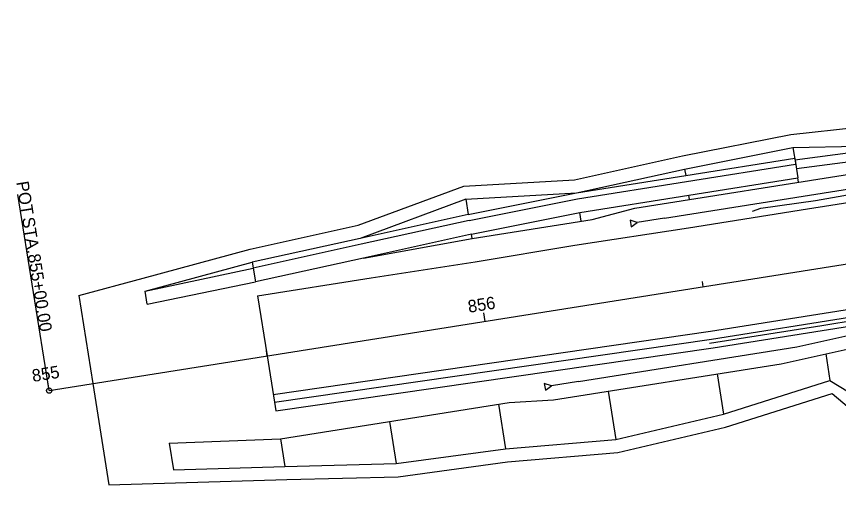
# Model space of a CAD drawing. Extents: x 115987 to 120394, y 324408 to 325987.
# Drawn here: x 117045 to 117231.2, y 325394.5 to 325501.7 of the extents above; entities that cross this region are included whole.
import ezdxf

# ---------------------------------------------------------------- set-up
doc = ezdxf.new("R2010")
doc.units = 0
for name, color, linetype in [('DT_X_Break_Line', 7, 'Continuous'), ('DT_X_Contour_Major', 7, 'Continuous'), ('DT_X_Contour_Minor', 7, 'Continuous'), ('DT_X_Terrain_Boundary', 7, 'Continuous'), ('DT_X_Triangles', 7, 'Continuous'), ('DT_X_Void', 7, 'Continuous'), ('PV_X_EOP', 7, 'Continuous'), ('PV_X_Shoulder', 7, 'Continuous'), ('RD_X_GR_Lt', 7, 'Continuous'), ('RW_X_CL_100_Stations', 7, 'Continuous'), ('RW_X_Esmt_LA', 7, 'Continuous'), ('RW_X_Text', 7, 'Continuous'), ('SV_X_Break_Lines', 7, 'Continuous'), ('UT_X_Gas_Cells', 7, 'Continuous')]:
    doc.layers.add(name, color=color, linetype=linetype)

msp = doc.modelspace()

# ---------------------------------------------------------------- linework, layer by layer
at = {"layer": 'DT_X_Break_Line'}
msp.add_lwpolyline([(117211.7, 325457.57), (117213.56, 325458.2), (117225.96, 325459.99), (117250.72, 325464.38), (117309.04, 325474.06), (117338.5, 325478.7), (117369.33, 325483.52), (117399.67, 325488.05), (117423.5, 325491.85)], dxfattribs=at)
at = {"layer": 'DT_X_Contour_Major'}
msp.add_line((117052.43, 325416.91), (117570.94, 325499.21), dxfattribs=at)
at = {"layer": 'DT_X_Contour_Minor'}
for p, q in [((117202.77, 325426.6), (117400.3, 325457.95)), ((117103.78, 325412.3), (117202.77, 325426.6)), ((117103.47, 325414.27), (117103.78, 325412.3))]:
    msp.add_line(p, q, dxfattribs=at)
at = {"layer": 'DT_X_Terrain_Boundary'}
for p, q in [((117200.57, 325440.42), (117200.39, 325441.61)), ((117151.19, 325432.59), (117150.88, 325434.56)), ((117101.81, 325424.75), (117101.62, 325425.93)), ((117052.43, 325416.91), (117052.11, 325418.89))]:
    msp.add_line(p, q, dxfattribs=at)
at = {"layer": 'DT_X_Triangles'}
for p, q in [((117202.17, 325430.35), (117399.7, 325461.7)), ((117202.45, 325428.57), (117399.98, 325459.92)), ((117099.65, 325438.36), (117101.81, 325424.75)), ((117103.19, 325416.05), (117202.17, 325430.35)), ((117103.47, 325414.27), (117202.45, 325428.57)), ((117101.81, 325424.75), (117103.47, 325414.27))]:
    msp.add_line(p, q, dxfattribs=at)
msp.add_lwpolyline([(117099.65, 325438.36), (117125.38, 325442.42), (117148.92, 325446.09), (117171.45, 325449.83), (117197.23, 325453.75), (117224.14, 325458.05), (117249.57, 325462.07), (117275.34, 325466.27), (117291.59, 325468.95), (117308.28, 325471.78), (117324.97, 325474.61), (117348.76, 325478.42), (117361.44, 325480.5), (117374.12, 325482.58), (117399.9, 325486.47), (117424.04, 325490.6), (117450.84, 325494.57), (117494.61, 325501.66)], dxfattribs=at)
at = {"layer": 'DT_X_Void'}
msp.add_line((117052.43, 325416.91), (117045.37, 325461.35), dxfattribs=at)
msp.add_circle((117052.43, 325416.91), 0.6, dxfattribs=at)
at = {"layer": 'PV_X_EOP'}
for p, q in [((117196.34, 325467.09), (117220.88, 325471.95)), ((117220.88, 325471.95), (117246.12, 325472.46)), ((117220.88, 325471.95), (117221.5, 325468.05)), ((117171.89, 325461.69), (117196.34, 325467.09)), ((117185.09, 325458.22), (117236.62, 325466.4)), ((117196.34, 325467.09), (117196.58, 325465.61)), ((117222.13, 325464.1), (117221.97, 325465.08)), ((117146.79, 325460.29), (117171.89, 325461.69)), ((117197.44, 325460.18), (117197.28, 325461.16)), ((117146.79, 325460.29), (117122.9, 325451.38)), ((117146.79, 325460.29), (117147.35, 325456.78)), ((117172.9, 325455.27), (117172.59, 325457.25)), ((117175.37, 325455.66), (117185.09, 325458.22)), ((117148.21, 325451.35), (117175.37, 325455.66)), ((117123.6, 325446.94), (117148.21, 325451.35)), ((117148.21, 325451.35), (117148.06, 325452.34)), ((117074.17, 325439.41), (117098.44, 325445.98)), ((117074.63, 325436.48), (117099.14, 325441.54)), ((117218.2, 325422.97), (117234.5, 325426.57)), ((117228.3, 325425.2), (117229.25, 325419.21)), ((117166.67, 325414.79), (117218.2, 325422.97)), ((117203.71, 325420.67), (117205.15, 325411.58)), ((117205.15, 325411.58), (117229.25, 325419.21)), ((117229.25, 325419.21), (117257.34, 325401.74)), ((117179.02, 325416.75), (117180.75, 325405.82)), ((117104.79, 325405.98), (117156.64, 325414.21)), ((117154.17, 325413.82), (117155.78, 325403.7)), ((117156.64, 325414.21), (117166.67, 325414.79)), ((117180.75, 325405.82), (117205.15, 325411.58)), ((117129.48, 325409.9), (117130.99, 325400.37)), ((117079.63, 325405.03), (117104.79, 325405.98)), ((117104.79, 325405.98), (117105.78, 325399.7)), ((117155.78, 325403.7), (117180.75, 325405.82)), ((117130.99, 325400.37), (117155.78, 325403.7)), ((117080.59, 325398.96), (117105.78, 325399.7)), ((117105.78, 325399.7), (117130.99, 325400.37))]:
    msp.add_line(p, q, dxfattribs=at)
at = {"layer": 'PV_X_Shoulder'}
for p, q in [((117221.32, 325469.18), (117246.12, 325472.46)), ((117221.64, 325467.21), (117246.43, 325470.48))]:
    msp.add_line(p, q, dxfattribs=at)
at = {"layer": 'RD_X_GR_Lt'}
for p, q in [((117196.58, 325465.61), (117221.27, 325469.53)), ((117196.78, 325464.3), (117221.48, 325468.19)), ((117221.27, 325469.53), (117221.97, 325465.08)), ((117171.89, 325461.69), (117196.58, 325465.61)), ((117172.09, 325460.38), (117196.78, 325464.3)), ((117197.28, 325461.16), (117221.97, 325465.08)), ((117147.35, 325456.78), (117171.89, 325461.69)), ((117147.56, 325455.47), (117172.09, 325460.38)), ((117172.59, 325457.25), (117197.28, 325461.16)), ((117147.35, 325456.78), (117122.9, 325451.38)), ((117148.06, 325452.34), (117172.59, 325457.25)), ((117147.56, 325455.47), (117123.1, 325450.07)), ((117122.9, 325451.38), (117098.44, 325445.98)), ((117148.06, 325452.34), (117123.6, 325446.94)), ((117123.1, 325450.07), (117098.65, 325444.67)), ((117098.44, 325445.98), (117099.14, 325441.54)), ((117123.6, 325446.94), (117099.14, 325441.54)), ((117074.17, 325439.41), (117098.65, 325444.67))]:
    msp.add_line(p, q, dxfattribs=at)
at = {"layer": 'RW_X_CL_100_Stations'}
for p, q in [((117074.63, 325436.48), (117074.17, 325439.41)), ((117079.63, 325405.03), (117080.59, 325398.96))]:
    msp.add_line(p, q, dxfattribs=at)
at = {"layer": 'RW_X_Esmt_LA'}
for p, q in [((117221.72, 325426.82), (117233.95, 325429.52)), ((117172.34, 325418.98), (117221.72, 325426.82)), ((117166.16, 325418), (117164.56, 325418.51)), ((117164.56, 325418.51), (117164.8, 325417.03)), ((117164.8, 325417.03), (117166.16, 325418)), ((117172.34, 325418.98), (117166.16, 325418))]:
    msp.add_line(p, q, dxfattribs=at)
at = {"layer": 'RW_X_Text'}
for p, q in [((117191.78, 325455.99), (117241.16, 325463.82)), ((117185.6, 325455.01), (117184, 325455.51)), ((117184, 325455.51), (117184.24, 325454.03)), ((117184.24, 325454.03), (117185.6, 325455.01)), ((117191.78, 325455.99), (117185.6, 325455.01))]:
    msp.add_line(p, q, dxfattribs=at)
at = {"layer": 'SV_X_Break_Lines'}
msp.add_lwpolyline([(117201.97, 325427.68), (117227.38, 325431.66), (117252.1, 325435.74), (117280.03, 325440.3), (117292.79, 325442.11), (117309.87, 325444.81), (117326.13, 325447.51), (117353.09, 325451.69), (117415.24, 325461.3), (117441.01, 325465.67), (117487.67, 325473.31)], dxfattribs=at)
at = {"layer": 'UT_X_Gas_Cells'}
for p, q in [((117220.41, 325474.91), (117245.29, 325477.68)), ((117195.87, 325470.05), (117220.41, 325474.91)), ((117171.42, 325464.65), (117195.87, 325470.05)), ((117146.32, 325463.25), (117171.42, 325464.65)), ((117122.43, 325454.35), (117146.32, 325463.25)), ((117097.97, 325448.95), (117122.43, 325454.35)), ((117073.7, 325442.37), (117097.97, 325448.95)), ((117059.14, 325438.43), (117073.7, 325442.37)), ((117059.14, 325438.43), (117062.3, 325418.48)), ((117062.3, 325418.48), (117065.94, 325395.56)), ((117205.62, 325408.61), (117229.72, 325416.24)), ((117229.72, 325416.24), (117255.68, 325394.49)), ((117181.22, 325402.86), (117205.62, 325408.61)), ((117156.25, 325400.74), (117181.22, 325402.86)), ((117131.46, 325397.41), (117156.25, 325400.74)), ((117106.26, 325396.74), (117131.46, 325397.41)), ((117065.94, 325395.56), (117081.06, 325396)), ((117081.06, 325396), (117106.26, 325396.74))]:
    msp.add_line(p, q, dxfattribs=at)

# ---------------------------------------------------------------- texts
at = {"layer": 'DT_X_Terrain_Boundary'}
for s, p in [('856', (117147.48, 325434.53)), ('855', (117048.77, 325418.86))]:
    msp.add_text(s, height=2.8, rotation=9.0184, dxfattribs=at).set_placement(p)
at = {"layer": 'DT_X_Void'}
for s, p in [('POT', (117044.98, 325464.13)), (' STA. ', (117046.11, 325457.01)), ('855+00.00', (117047.59, 325447.68))]:
    msp.add_text(s, height=2.8, rotation=279.0184, dxfattribs=at).set_placement(p)

doc.saveas('drawing.dxf')
